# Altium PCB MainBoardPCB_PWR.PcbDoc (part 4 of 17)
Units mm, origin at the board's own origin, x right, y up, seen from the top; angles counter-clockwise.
Board outline 333.63 x 349.38 mm, 16 copper layers (L1, L2 (GND), L3 (Sign), L4 (GND), L5 (Sign), L6 (PWR/GND), L7(PWR/GND), L8 (PWR/GND), L9 (PWR/GND), L10 (PWR/GND), L11 (PWR/GND), L12 (Sign), L13 (GND), L14 (Sign), L15 (GND), L16), stack 2.503 mm thick; 2187 components, 1615 nets, 7987 pads, 1695 vias.
Unrouted connection lines stored in the file: 4757.
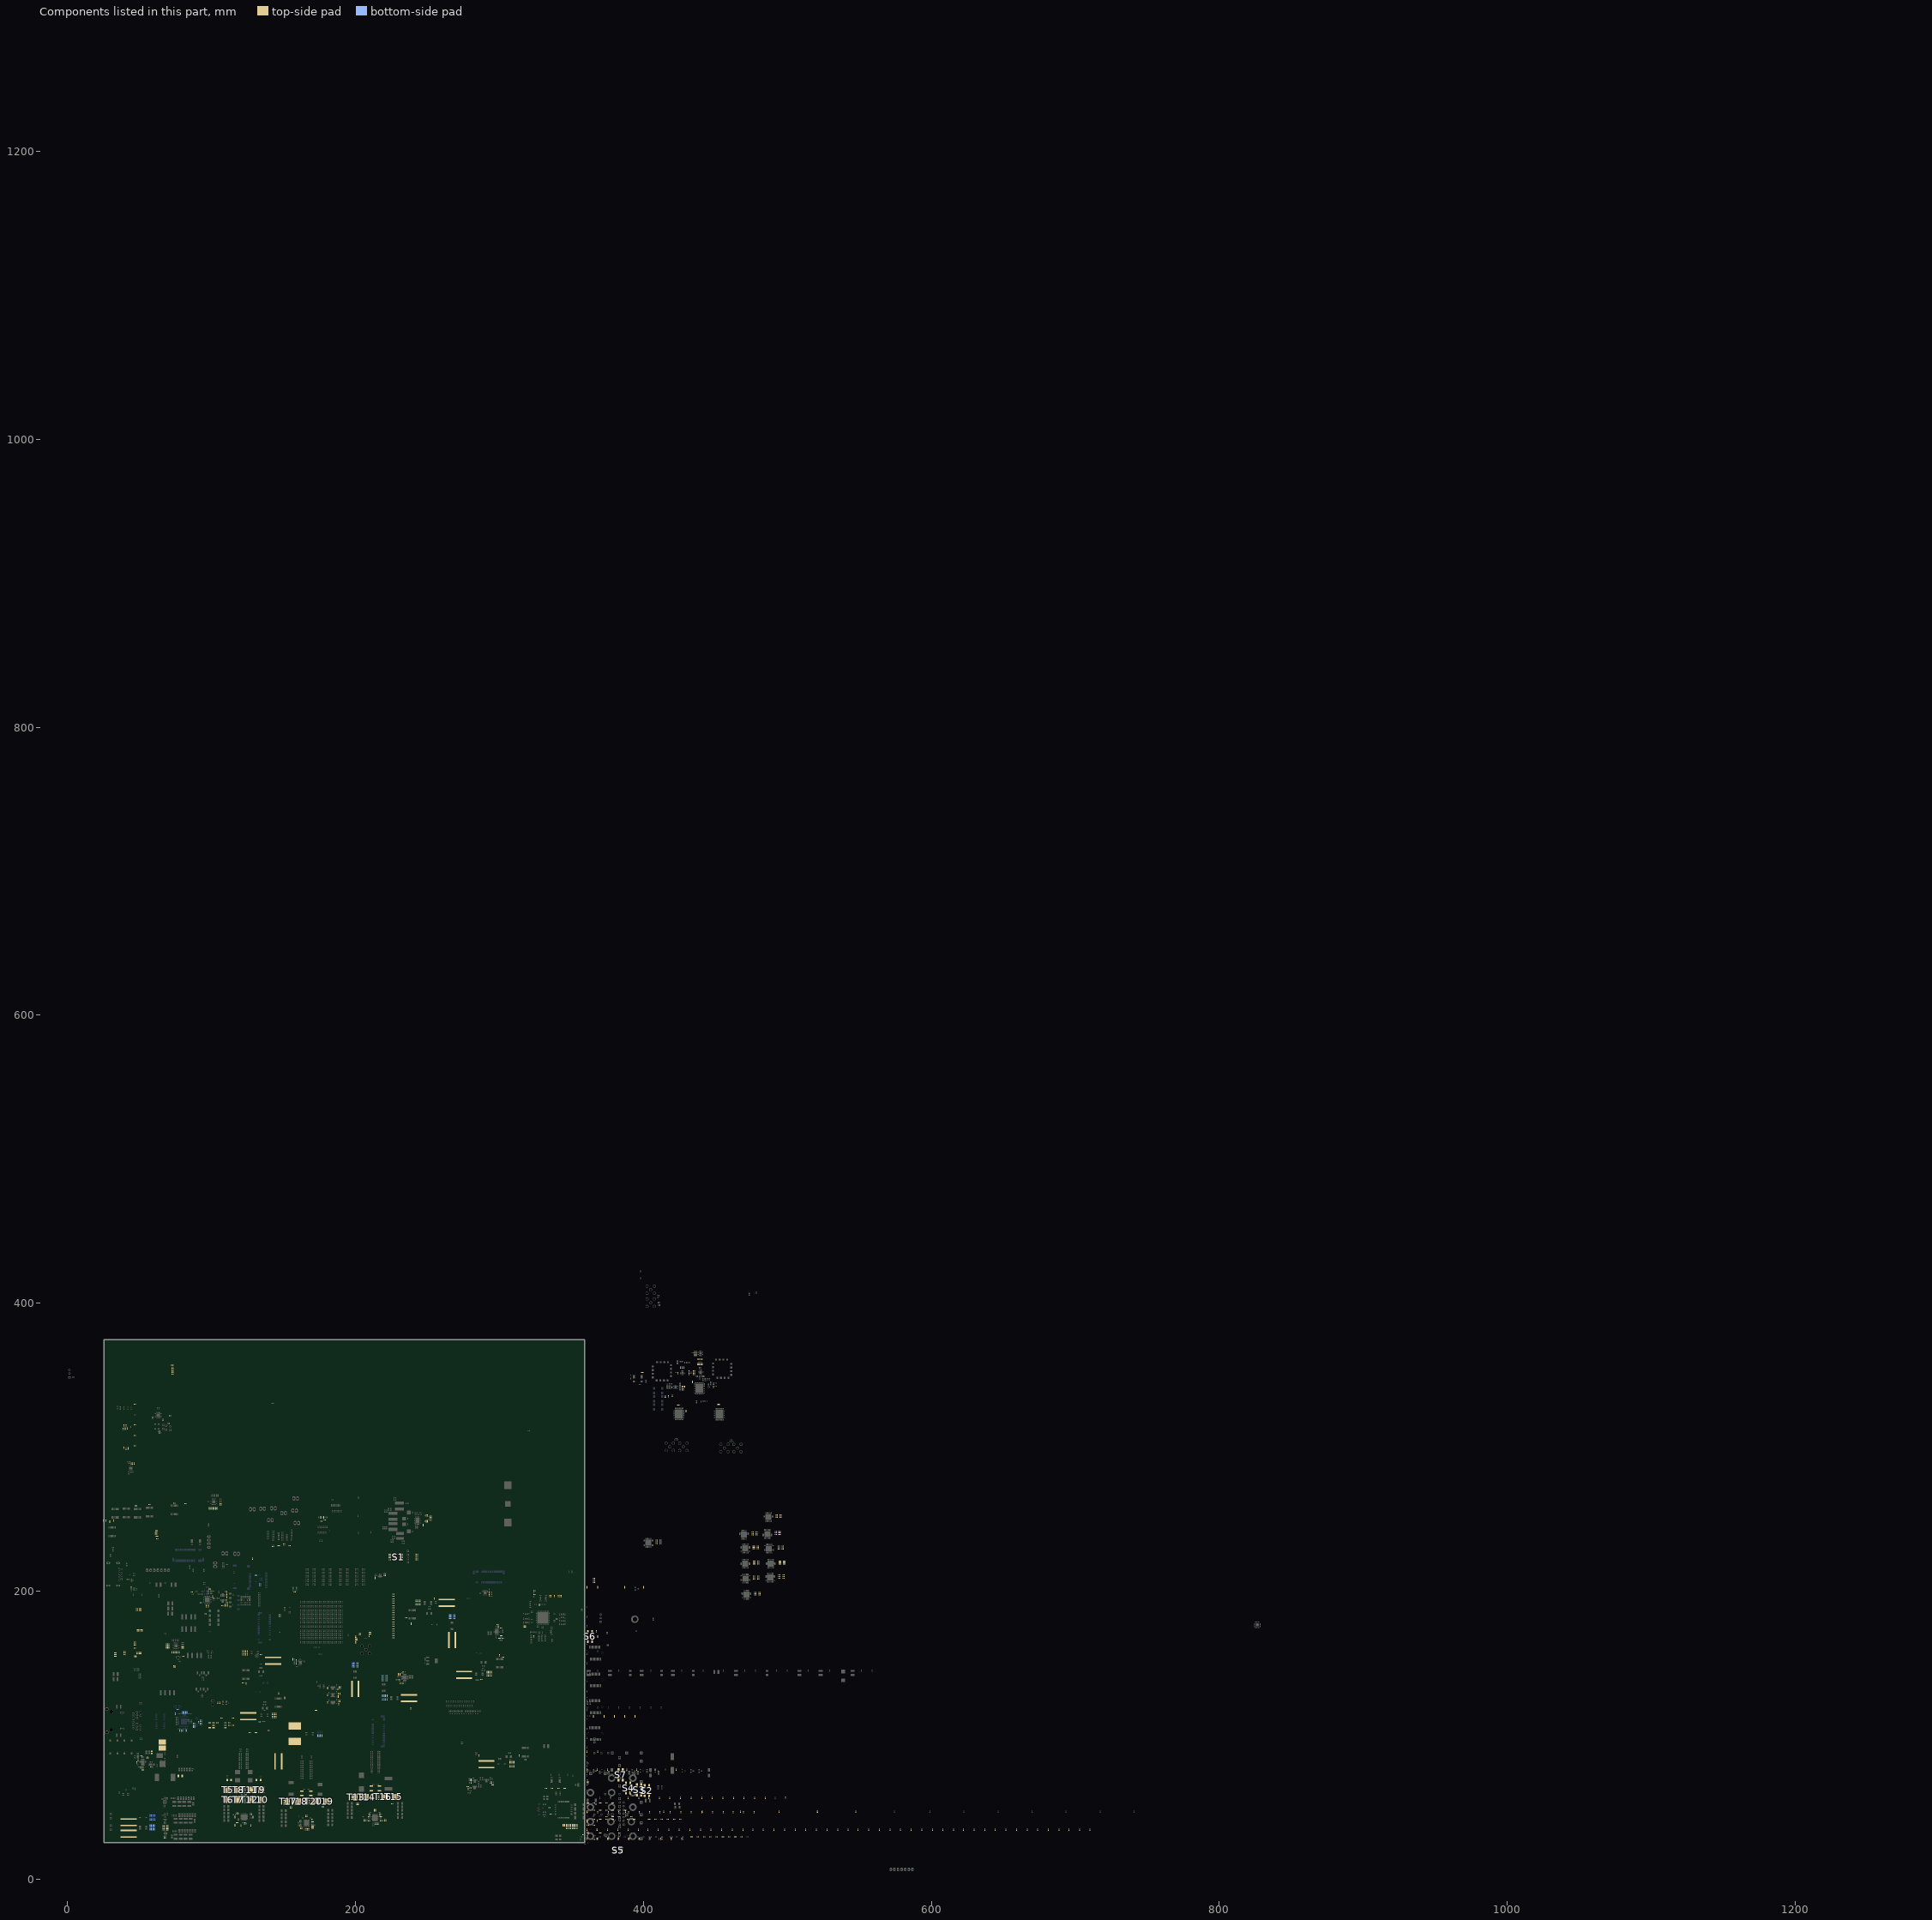
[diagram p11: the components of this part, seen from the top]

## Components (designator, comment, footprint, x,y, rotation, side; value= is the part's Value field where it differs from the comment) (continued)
R122 "30R" "RES 0402/1005 RF" 86.36,199.263 r0 top
R123 "4.7kR" "RES 0402/1005 RF" 107.442,189.738 r0 top
R124 "1kR" "RES 0402/1005 RF" 172.593,117.221 r180 top
R125 "10kR" "RES 0402/1005 RF" 339.728,180.764 r180 top
R126 "100R" "RES 0402/1005 RF" 335.899,196.61 r270 top
R127 "0R" "RES 0402/1005 RF" 367.995,40.538 r90 top
R128 "10kR" "RES 0402/1005 RF" 317.608,174.88 r180 top
R129 "10kR" "RES 0402/1005 RF" 317.608,175.819 r180 top
R130 "0R" "RES 0402/1005 RF" 334.902,196.597 r270 top
R131 "0R" "RES 0402/1005 RF" 338.144,196.597 r270 top
R132 "0R" "RES 0402/1005 RF" 342.005,196.483 r90 top
R133 "0R" "RES 0402/1005 RF" 343.021,196.483 r90 top
R134 "0R" "RES 0402/1005 RF" 340.998,196.528 r90 top
R135 "4.7kR" "RES 0402/1005 RF" 47.255,154.305 r0 top
R136 "4.7kR" "RES 0402/1005 RF" 46.99,155.067 r0 top
R137 "4.7kR" "RES 0402/1005 RF" 46.805,160.274 r0 top
R138 "4.7kR" "RES 0402/1005 RF" 33.216,154.695 r0 top
R139 "0R" "RES 0402/1005 RF" 360.883,40.538 r90 top
R140 "2.2R" "RES 0402/1005 RF" 55.575,84.026 r0 top
R141 "0R" "RES 0402/1005 RF" 50.549,156.46 r0 top
R142 "0R" "RES 0402/1005 RF" 50.549,157.494 r0 top
R143 "0R" "RES 0402/1005 RF" 48.575,156.478 r0 top
R144 "0R" "RES 0402/1005 RF" 48.575,157.494 r0 top
R145 "4.7kR" "RES 0402/1005 RF" 46.736,164.465 r0 top
R146 "4.7kR" "RES 0402/1005 RF" 46.736,162.56 r0 top
R147 "4.7kR" "RES 0402/1005 RF" 46.736,163.449 r0 top
R148 "4.7kR" "RES 0402/1005 RF" 33.216,156.981 r0 top
R149 "196kR" "RES 0402/1005 RF" 52.232,84.777 r0 top
R150 "22k" "RES 0402/1005 RF" 52.332,75.895 r0 top
R151 "0R" "RES 0402/1005 RF" 51.393,173.303 r0 top
R152 "0R" "RES 0402/1005 RF" 51.346,172.287 r0 top
R153 "0R" "RES 0402/1005 RF" 48.98,173.303 r0 top
R154 "0R" "RES 0402/1005 RF" 48.98,172.287 r0 top
R155 "4.7kR" "RES 0402/1005 RF" 39.693,158.115 r0 top
R156 "4.7kR" "RES 0402/1005 RF" 39.693,157.099 r0 top
R157 "4.7kR" "RES 0402/1005 RF" 39.684,155.829 r0 top
R158 "4.7kR" "RES 0402/1005 RF" 33.216,155.956 r0 top
R159 "10kR" "RES 0402/1005 RF" 51.307,85.787 r0 top
R160 "910R" "RES 0402/1005 RF" 51.883,77.43 r90 top
R161 "0R" "RES 0402/1005 RF" 50.473,187.654 r0 top
R162 "0R" "RES 0402/1005 RF" 50.473,186.638 r0 top
R163 "0R" "RES 0402/1005 RF" 48.234,187.654 r0 top
R164 "0R" "RES 0402/1005 RF" 48.234,186.638 r0 top
R165 "100R" "RES 0402/1005 RF" 178.738,249.428 r0 top
R166 "100R" "RES 0402/1005 RF" 176.394,248.666 r0 top
R167 "100R" "RES 0402/1005 RF" 178.029,251.222 r90 top
R168 "100R" "RES 0402/1005 RF" 175.87,251.222 r90 top
R169 "100R" "RES 0402/1005 RF" 150.495,232.621 r0 top
R170 "100R" "RES 0402/1005 RF" 146.685,231.605 r0 top
R171 "100R" "RES 0402/1005 RF" 154.292,231.605 r0 top
R172 "100R" "RES 0402/1005 RF" 142.748,230.97 r0 top
R173 "500R" "RES 0402/1005 RF" 360.883,28.042 r90 top
R174 "0mR" "RES 0402/1005 RF" 242.95,190.832 r270 top
R175 "0mR" "RES 0402/1005 RF" 241.934,190.832 r270 top
R176 "0mR" "RES 0402/1005 RF" 245.03,190.832 r270 top
R177 "0mR" "RES 0402/1005 RF" 244.014,190.832 r270 top
R178 "0mR" "RES 0402/1005 RF" 242.95,193.209 r90 top
R179 "0mR" "RES 0402/1005 RF" 241.934,193.209 r90 top
R180 "0mR" "RES 0402/1005 RF" 245.03,193.209 r90 top
R181 "0mR" "RES 0402/1005 RF" 244.014,193.209 r90 top
R182 "1.02kR" "RES 0402/1005 RF" 254.912,194.739 r90 top
R183 "0mR" "RES 0402/1005 RF" 293.357,143.679 r90 top
R184 "0mR" "RES 0402/1005 RF" 294.357,143.679 r90 top
R185 "0mR" "RES 0402/1005 RF" 291.357,143.679 r90 top
R186 "0mR" "RES 0402/1005 RF" 292.357,143.679 r90 top
R187 "0mR" "RES 0402/1005 RF" 293.357,141.493 r270 top
R188 "0mR" "RES 0402/1005 RF" 294.357,141.493 r270 top
R189 "0mR" "RES 0402/1005 RF" 291.357,141.493 r270 top
R190 "0mR" "RES 0402/1005 RF" 292.357,141.493 r270 top
R191 "1.02kR" "RES 0402/1005 RF" 287.374,138.68 r0 top
R192 "0mR" "RES 0402/1005 RF" 122.794,156.081 r270 top
R193 "0mR" "RES 0402/1005 RF" 121.735,156.081 r270 top
R194 "0mR" "RES 0402/1005 RF" 124.91,156.081 r270 top
R195 "0mR" "RES 0402/1005 RF" 123.852,156.081 r270 top
R196 "0mR" "RES 0402/1005 RF" 122.794,158.113 r90 top
R197 "0mR" "RES 0402/1005 RF" 121.735,158.113 r90 top
R198 "0mR" "RES 0402/1005 RF" 124.91,158.113 r90 top
R199 "0mR" "RES 0402/1005 RF" 123.852,158.113 r90 top
R200 "1.02kR" "RES 0402/1005 RF" 134.297,155.956 r0 top
R201 "0mR" "RES 0402/1005 RF" 144.008,114.727 r90 top
R202 "0mR" "RES 0402/1005 RF" 144.958,114.727 r90 top
R203 "0mR" "RES 0402/1005 RF" 142.088,114.727 r90 top
R204 "0mR" "RES 0402/1005 RF" 143.053,114.732 r90 top
R205 "0mR" "RES 0402/1005 RF" 144.008,112.571 r270 top
R206 "0mR" "RES 0402/1005 RF" 144.958,112.571 r270 top
R207 "0mR" "RES 0402/1005 RF" 142.088,112.568 r270 top
R208 "0mR" "RES 0402/1005 RF" 143.053,112.568 r270 top
R209 "1.02kR" "RES 0402/1005 RF" 133.501,109.15 r180 top
R210 "0mR" "RES 0402/1005 RF" 309.27,81.218 r90 top
R211 "0mR" "RES 0402/1005 RF" 310.314,81.218 r90 top
R212 "12.5k" "RES 0402/1005 RF" 251.788,251.574 r90 top
R213 "0mR" "RES 0402/1005 RF" 307.166,81.218 r90 top
R214 "10kR" "RES 0402/1005 RF" 252.738,251.574 r270 top
R215 "0mR" "RES 0402/1005 RF" 308.227,81.218 r90 top
R216 "31.2kR" "RES 0402/1005 RF" 249.13,252.624 r270 top
R217 "0mR" "RES 0402/1005 RF" 309.27,78.437 r270 top
R218 "10kR" "RES 0402/1005 RF" 250.096,252.624 r270 top
R219 "0mR" "RES 0402/1005 RF" 310.314,78.437 r270 top
R220 "4.99kR" "RES 0402/1005 RF" 249.13,248.499 r270 top
R221 "0mR" "RES 0402/1005 RF" 307.166,78.441 r270 top
R222 "0mR" "RES 0402/1005 RF" 308.227,78.441 r270 top
R223_I2C_Bridge "1kR" "RES 0402/1005 RF" 106.426,260.867 r0 top (schematic designator R223)
R223_I2C_Bridge_2 "1kR" "RES 0402/1005 RF" 547.548,46.787 r90 top (schematic designator R223)
R223_I2C_Bridge_3 "1kR" "RES 0402/1005 RF" 79.952,161.248 r0 top (schematic designator R223)
R224_I2C_Bridge "1kR" "RES 0402/1005 RF" 106.426,259.812 r0 top (schematic designator R224)
R224_I2C_Bridge_2 "1kR" "RES 0402/1005 RF" 520.878,46.787 r90 top (schematic designator R224)
R224_I2C_Bridge_3 "1kR" "RES 0402/1005 RF" 79.952,160.274 r0 top (schematic designator R224)
R225_I2C_Bridge "1kR" "RES 0402/1005 RF" 103.886,257.487 r270 top (schematic designator R225)
R225_I2C_Bridge_2 "1kR" "RES 0402/1005 RF" 494.208,46.787 r90 top (schematic designator R225)
R225_I2C_Bridge_3 "1kR" "RES 0402/1005 RF" 77.471,157.607 r270 top (schematic designator R225)
R226_I2C_Bridge "1kR" "RES 0402/1005 RF" 102.85,257.487 r270 top (schematic designator R226)
R226_I2C_Bridge_2 "1kR" "RES 0402/1005 RF" 467.538,46.787 r90 top (schematic designator R226)
R226_I2C_Bridge_3 "1kR" "RES 0402/1005 RF" 76.506,157.607 r270 top (schematic designator R226)
R227_I2C_Bridge "1kR" "RES 0402/1005 RF" 101.85,257.487 r270 top (schematic designator R227)
R227_I2C_Bridge_2 "1kR" "RES 0402/1005 RF" 440.893,46.787 r90 top (schematic designator R227)
R227_I2C_Bridge_3 "1kR" "RES 0402/1005 RF" 75.54,157.607 r270 top (schematic designator R227)
R228 "1.02kR" "RES 0402/1005 RF" 285.883,85.729 r90 top
R229 "0mR" "RES 0402/1005 RF" 59.385,37.078 r90 bottom
R230 "0mR" "RES 0402/1005 RF" 60.465,37.078 r90 bottom
R231_SPI_bridge1 "1kR" "RES 0402/1005 RF" 238.618,177.387 r90 top (schematic designator R231)
R231_SPI_bridge2 "1kR" "RES 0402/1005 RF" 411.039,398.754 r0 top (schematic designator R231)
R231_SPI_bridge3 "1kR" "RES 0402/1005 RF" 74.237,261.112 r180 top (schematic designator R231)
R232_SPI_bridge1 "1kR" "RES 0402/1005 RF" 235.247,181.451 r0 top (schematic designator R232)
R232_SPI_bridge2 "1kR" "RES 0402/1005 RF" 410.716,400.405 r0 top (schematic designator R232)
R232_SPI_bridge3 "1kR" "RES 0402/1005 RF" 62.103,238.125 r0 top (schematic designator R232)
R233_SPI_bridge1 "1kR" "RES 0402/1005 RF" 299.974,155.533 r270 top (schematic designator R233)
R233_SPI_bridge2 "1kR" "RES 0402/1005 RF" 420.04,335.691 r90 top (schematic designator R233)
R233_SPI_bridge3 "1kR" "RES 0402/1005 RF" 96.012,184.333 r180 top (schematic designator R233)
R234_SPI_bridge1 "1kR" "RES 0402/1005 RF" 302.583,154.136 r180 top (schematic designator R234)
R234_SPI_bridge2 "1kR" "RES 0402/1005 RF" 415.158,335.114 r90 top (schematic designator R234)
R234_SPI_bridge3 "1kR" "RES 0402/1005 RF" 61.838,241.935 r0 top (schematic designator R234)
R235_SPI_bridge1 "1kR" "RES 0402/1005 RF" 121.772,136.265 r0 top (schematic designator R235)
R235_SPI_bridge2 "1kR" "RES 0402/1005 RF" 417.444,335.437 r90 top (schematic designator R235)
R235_SPI_bridge3 "1kR" "RES 0402/1005 RF" 62.288,236.453 r0 top (schematic designator R235)
R236_SPI_bridge1 "1kR" "RES 0402/1005 RF" 123.952,135.763 r90 top (schematic designator R236)
R236_SPI_bridge2 "1kR" "RES 0402/1005 RF" 433.984,345.313 r90 top (schematic designator R236)
R236_SPI_bridge3 "1kR" "RES 0402/1005 RF" 47.498,259.207 r180 top (schematic designator R236)
R237_SPI_bridge1 "1kR" "RES 0402/1005 RF" 151.003,125.857 r90 top (schematic designator R237)
R237_SPI_bridge2 "1kR" "RES 0402/1005 RF" 32.004,248.92 r90 top (schematic designator R237)
R237_SPI_bridge3 "1kR" "RES 0402/1005 RF" 61.503,240.792 r0 top (schematic designator R237)
R238_SPI_bridge1 "1kR" "RES 0402/1005 RF" 146.685,129.032 r270 top (schematic designator R238)
R238_SPI_bridge2 "1kR" "RES 0402/1005 RF" 29.464,248.285 r90 top (schematic designator R238)
R238_SPI_bridge3 "1kR" "RES 0402/1005 RF" 56.896,260.096 r180 top (schematic designator R238)
R239_SPI_bridge1 "1kR" "RES 0402/1005 RF" 313.893,85.725 r270 top (schematic designator R239)
R239_SPI_bridge2 "1kR" "RES 0402/1005 RF" 26.543,249.047 r90 top (schematic designator R239)
R239_SPI_bridge3 "1kR" "RES 0402/1005 RF" 61.503,239.649 r0 top (schematic designator R239)
R240_SPI_bridge1 "1kR" "RES 0402/1005 RF" 318.028,83.058 r0 top (schematic designator R240)
R240_SPI_bridge2 "1kR" "RES 0402/1005 RF" 25.019,248.92 r90 top (schematic designator R240)
R240_SPI_bridge3 "1kR" "RES 0402/1005 RF" 81.973,260.858 r180 top (schematic designator R240)
R241 "0mR" "RES 0402/1005 RF" 411.963,28.042 r90 top
R242 "0mR" "RES 0402/1005 RF" 404.597,28.042 r90 top
R243 "0mR" "RES 0402/1005 RF" 397.205,28.042 r90 top
R244 "0mR" "RES 0402/1005 RF" 389.839,28.042 r90 top
R245 "100R" "RES 0402/1005 RF" 439.318,355.092 r180 top
R246 "120R" "RES 0402/1005 RF" 440.303,361.061 r180 top
R247 "127R" "RES 0402/1005 RF" 440.303,357.251 r180 top
R248 "127R" "RES 0402/1005 RF" 438.202,357.251 r0 top
R249 "120R" "RES 0402/1005 RF" 438.202,361.061 r180 top
R250 "82.5R" "RES 0402/1005 RF" 440.303,358.267 r180 top
R251 "82.5R" "RES 0402/1005 RF" 438.202,358.267 r0 top
R252 "1kR" "RES 0402/1005 RF" 435.635,366.083 r90 top
R253 "1kR" "RES 0402/1005 RF" 435.635,364.079 r270 top
R254 "1kR" "RES 0402/1005 RF" 436.651,366.083 r270 top
R255 "1kR" "RES 0402/1005 RF" 436.651,364.079 r90 top
R256 "120R" "RES 0402/1005 RF" 431.825,350.774 r90 top
R257 "49.9R" "RES 0402/1005 RF" 423.951,351.467 r90 top
R258 "120R" "RES 0402/1005 RF" 431.825,352.711 r90 top
R259 "82.5R" "RES 0402/1005 RF" 435.635,352.711 r270 top
R260 "82.5R" "RES 0402/1005 RF" 435.635,350.774 r90 top
R261 "127R" "RES 0402/1005 RF" 434.619,352.711 r270 top
R262 "127R" "RES 0402/1005 RF" 434.619,350.774 r90 top
R263 "60.4kR" "RES 0402/1005 RF" 425.602,355.288 r270 top
R264 "0mR" "RES 0402/1005 RF" 428.112,355.288 r270 top
R265 "0mR" "RES 0402/1005 RF" 426.887,355.288 r270 top
R266 "84.5kR" "RES 0402/1005 RF" 383.235,32.182 r0 top
R267 "4.7kR" "RES 0402/1005 RF" 370.04,32.182 r0 top
R268 "2R" "RES 0402/1005 RF" 120.402,37.326 r90 top
R269 "1.02kR" "RES 0402/1005 RF" 361.391,32.182 r0 top
R270 "160R" "RES 0402/1005 RF" 238.506,118.618 r270 top
R271 "5kR" "RES 0402/1005 RF" 117.796,39.126 r180 top
R272 "2R" "RES 0402/1005 RF" 122.978,38.69 r270 top
R273 "12kR" "RES 0402/1005 RF" 118.596,41.473 r270 top
R274 "10kR" "RES 0402/1005 RF" 250.096,248.503 r90 top
R275 "47kR" "RES 0402/1005 RF" 121.202,58.572 r180 top
R276 "4.7kR" "RES 0402/1005 RF" 387.363,47.739 r0 top
R277 "12kR" "RES 0402/1005 RF" 128.799,43.024 r90 top
R278 "12kR" "RES 0402/1005 RF" 116.439,43.024 r90 top
R279 "0mR" "RES 0402/1005 RF" 383.045,47.739 r0 top
R280 "47kR" "RES 0402/1005 RF" 123.777,58.572 r0 top
R281 "0mR" "RES 0402/1005 RF" 382.981,28.042 r90 top
R282 "0mR" "RES 0402/1005 RF" 378.714,47.739 r0 top
R283 "0mR" "RES 0402/1005 RF" 374.383,47.739 r0 top
R284 "18.2k (1MHz)" "RES 0402/1005 RF" 247.126,245.841 r90 top
R285 "2R" "RES 0402/1005 RF" 201.462,51.702 r0 top
R286 "0mR" "RES 0402/1005 RF" 370.053,47.739 r0 top
R287 "49.9kR" "RES 0402/1005 RF" 205.838,40.864 r90 top
R288 "Resistor_1210" RES_1210 211.045,63.039 r270 top value=3.6R
R289 "2R" "RES 0402/1005 RF" 213.795,38.516 r270 top
R290 "10kR" "RES 0402/1005 RF" 206.788,40.864 r270 top
R291 "150R" "RES 0402/1005 RF" 365.722,47.739 r0 top
R292 "Resistance" "RES 0402/1005 RF" 213.195,47.846 r270 top
R293 "0mR" "RES 0402/1005 RF" 214.795,38.516 r90 top
R294 "0mR" "RES 0402/1005 RF" 215.795,38.516 r90 top
R295 "12kR" "RES 0402/1005 RF" 209.441,43.359 r0 top
R296 "12kR" "RES 0402/1005 RF" 217.555,43.359 r180 top
R297 "10kR" "RES 0402/1005 RF" 221.201,40.765 r90 top
R298 "Resistor_1210" RES_1210 216.76,63.039 r270 top value=3.6R
R299 "47kR" "RES 0402/1005 RF" 214.045,47.846 r270 top
R300 "10kR" "RES 0402/1005 RF" 220.17,40.765 r270 top
R301 "150R" "RES 0402/1005 RF" 391.655,43.434 r0 top
R302 "1.4kR" "RES 0201/0603" 170.009,41.515 r180 top
R303 "2R" "RES 0402/1005 RF" 155.178,49.178 r0 top
R304 "0mR" "RES 0402/1005 RF" 175.712,99.689 r270 bottom
R305 "100R" "RES 0402/1005 RF" 383.019,43.434 r0 top
R306 "Resistor_1210" RES_1210 162.816,59.629 r270 top value=3.6R
R307 "2R" "RES 0402/1005 RF" 165.608,34.537 r270 top
R308 "100R" "RES 0402/1005 RF" 378.689,43.434 r0 top
R309 "100R" "RES 0402/1005 RF" 374.358,43.434 r0 top
R310 "0mR" "RES 0402/1005 RF" 166.533,34.537 r90 top
R311 "100R" "RES 0402/1005 RF" 361.391,67.488 r0 top
R312 "0mR" "RES 0402/1005 RF" 167.448,34.537 r90 top
R313 "12kR" "RES 0402/1005 RF" 161.743,40.015 r0 top
R314 "12kR" "RES 0402/1005 RF" 170.224,39.685 r180 top
R315 "196kR" "RES 0402/1005 RF" 170.224,36.103 r0 top
R316 "Resistor_1210" RES_1210 169.006,59.629 r270 top value=3.6R
R317 "47kR" "RES 0402/1005 RF" 166.458,43.718 r270 top
R318 "27kR" "RES 0402/1005 RF" 170.224,35.175 r180 top
R319 "10kR" "RES 0402/1005 RF" 92.075,109.935 r90 bottom
R320 "10kR" "RES 0402/1005 RF" 92.075,107.893 r270 bottom
R321 "100R" "RES 0402/1005 RF" 90.932,109.035 r90 bottom
R322 "5.76kR" "RES 0402/1005 RF" 88.392,107.765 r90 bottom
R323 "5.76kR" "RES 0402/1005 RF" 87.376,105.915 r270 bottom
R324 "100kR" "RES 0805/2012 RF" 58.578,87.994 r270 top
R325 "2.49kR" "RES 0402/1005 RF" 93.028,109.924 r270 bottom
R326 "2.49kR" "RES 0402/1005 RF" 93.028,107.893 r90 bottom
R327 "2.49kR" "RES 0402/1005 RF" 87.376,107.765 r270 bottom
R328 "2.49kR" "RES 0402/1005 RF" 88.392,105.915 r90 bottom
R329 "100R" "RES 0402/1005 RF" 78.022,103.113 r270 bottom
R330 "100R" "RES 0402/1005 RF" 79.022,103.113 r270 bottom
R331 "100R" "RES 0402/1005 RF" 80.022,103.113 r270 bottom
R332 "100R" "RES 0402/1005 RF" 82.522,103.113 r90 bottom
R333 "2.2kR" "RES 0402/1005 RF" 80.007,115.766 r270 bottom
R334 "11kR" "RES 0402/1005" 74.93,114.741 r90 bottom
R335 "1MR" "RES 0402/1005 RF" 76.516,117.836 r180 bottom
R336 "2.2kR" "RES 0402/1005 RF" 83.038,115.766 r270 bottom
R337 "2.2kR" "RES 0402/1005 RF" 81.022,115.766 r270 bottom
R338 "2.2kR" "RES 0402/1005 RF" 82.022,115.766 r270 bottom
R339 "105kR" "RES 0402/1005 RF" 110.692,198.11 r90 top
R340 "10kR" "RES 0402/1005 RF" 110.226,199.669 r0 top
R341 "15kR" "RES 0402/1005 RF" 110.692,196.185 r90 top
R342 "105kR" "RES 0402/1005 RF" 110.392,193.552 r90 top
R343 "10kR" "RES 0402/1005 RF" 110.957,190.202 r270 top
R344 "15kR" "RES 0402/1005 RF" 110.84,192.073 r180 top
R345 "0R" "RES 0402/1005 RF" 109.572,190.186 r90 top
R346 "4.7kR" "RES 0402/1005 RF" 70.254,316.535 r0 top
R347 "4.7kR" "RES 0402/1005 RF" 147.389,182.53 r0 top
R348 "4.7kR" "RES 0402/1005 RF" 147.447,183.642 r0 top
R349 "4.7kR" "RES 0402/1005 RF" 242.639,221.742 r0 top
R350 "4.7kR" "RES 0402/1005 RF" 242.639,223.054 r0 top
R351 "4.7kR" "RES 0402/1005 RF" 242.639,224.367 r0 top
R352 "4.7kR" "RES 0402/1005 RF" 242.639,225.679 r0 top
R353 "4.7kR" "RES 0402/1005 RF" 39.301,299.653 r90 top
R354 "4.7kR" "RES 0402/1005 RF" 63.754,311.201 r0 top
R355 "4.7kR" "RES 0402/1005 RF" 64.135,309.931 r0 top
R356 "4.7kR" "RES 0402/1005 RF" 42.028,299.203 r270 top
R357 "4.7kR" "RES 0402/1005 RF" 40.728,298.753 r90 top
R358 "499R" "RES 0402/1005 RF" 224.045,221.86 r180 top
R359 "499R" "RES 0402/1005 RF" 223.845,223.139 r180 top
R360 "499R" "RES 0402/1005 RF" 223.845,224.409 r180 top
R361 "499R" "RES 0402/1005 RF" 223.845,225.679 r180 top
R362 "30R" "RES 0402/1005 RF" 38.539,312.801 r90 top
R363 "4.7kR" "RES 0402/1005 RF" 39.301,315.156 r90 top
R364 "4.7kR" "RES 0402/1005 RF" 40.078,312.87 r90 top
R365 "4.7kR" "RES 0402/1005 RF" 41.46,312.928 r90 top
R366 "10kR" "RES 0402/1005 RF" 40.825,315.087 r90 top
R367 "4.7kR" "RES 0402/1005 RF" 71.27,321.691 r0 top
R368 "261R" "RES 0402/1005 RF" 46.863,329.819 r180 top
R369 "10kR" "RES 0402/1005 RF" 66.317,318.948 r90 top
R370 "10kR" "RES 0402/1005 RF" 46.863,300.863 r180 top
R371 "10kR" "RES 0402/1005 RF" 46.863,308.229 r180 top
R372 "8.06kR" "RES 0402/1005 RF" 46.863,315.595 r180 top
R373 "10kR" "RES 0402/1005 RF" 59.078,320.472 r90 top
R374 "4.7MR" "RES 0402/1005 RF" 157.874,199.339 r0 top
R375 "40.2R" "RES 0402/1005 RF" 128.637,222.542 r270 top
R376 "0R" "RES 0402/1005 RF" 92.603,192.052 r180 top
R377 "0R" "RES 0402/1005 RF" 96.278,189.529 r270 top
R378 "0R" "RES 0402/1005 RF" 97.778,189.529 r270 top
R379 "8.06kR" "RES 0402/1005 RF" 100.851,196.372 r270 top
R380 "4.22kR" "RES 0402/1005 RF" 44.348,202.539 r270 top
R381 "4.7kR" "RES 0402/1005 RF" 133.789,205.105 r180 bottom
R382 "4.7kR" "RES 0402/1005 RF" 133.8,203.835 r180 bottom
R383 "10kR" "RES 0402/1005 RF" 130.937,211.074 r0 bottom
R384 "71.5R" "RES 0402/1005 RF" 365.76,208.915 r0 top
R385 "71.5R" "RES 0402/1005 RF" 365.76,207.899 r0 top
R386 "8.87kR" "RES 0402/1005 RF" 365.76,206.883 r0 top
R387 "5.1kR" "RES 0402/1005 RF" 365.76,205.867 r0 top
R388 "0mR" "RES 0402/1005 RF" 176.728,99.689 r270 bottom
R389 "0mR" "RES 0402/1005 RF" 174.687,99.695 r270 bottom
R390 "0mR" "RES 0402/1005 RF" 173.68,99.689 r270 bottom
R391 "75kR" "RES 0402/1005 RF" 188.725,132.945 r90 top
R392 "100kR" "RES 0402/1005 RF" 189.711,132.945 r90 top
R393 "15kR" "RES 0402/1005 RF" 187.696,131.995 r90 top
R394 "51.1kR" "RES 0402/1005 RF" 188.22,128.702 r90 top
R395 "10kR" "RES 0402/1005 RF" 189.244,128.704 r90 top
R396 "15kR" "RES 0402/1005 RF" 188.22,126.719 r90 top
R397 "21.5kR" "RES 0402/1005 RF" 188.266,123.575 r90 top
R398 "10kR" "RES 0402/1005 RF" 189.244,123.575 r90 top
R399 "15kR" "RES 0402/1005 RF" 188.266,121.609 r90 top
R400 "0mR" "RES 0402/1005 RF" 375.615,28.042 r90 top
R401 "10k" "RES 0402/1005 RF" 345.349,37.41 r90 top
R402 "0R" "RES 0402/1005 RF" 348.539,37.41 r270 top
R403 "0R" "RES 0402/1005 RF" 348.539,35.378 r90 top
R404 "0R" "RES 0402/1005 RF" 349.603,37.41 r270 top
R405 "0R" "RES 0402/1005 RF" 349.603,35.378 r90 top
R406 "0R" "RES 0402/1005 RF" 347.476,37.41 r270 top
R407 "0R" "RES 0402/1005 RF" 347.476,35.378 r90 top
R408 "0R" "RES 0402/1005 RF" 346.412,37.41 r270 top
R409 "0R" "RES 0402/1005 RF" 346.412,35.378 r90 top
R410 "10k" "RES 0402/1005 RF" 344.285,37.41 r90 top
R411 "0R" "RES 0402/1005 RF" 351.73,37.41 r270 top
R412 "0R" "RES 0402/1005 RF" 351.73,35.378 r90 top
R413 "0R" "RES 0402/1005 RF" 353.857,37.41 r270 top
R414 "0R" "RES 0402/1005 RF" 353.857,35.378 r90 top
R415 "0R" "RES 0402/1005 RF" 350.666,37.41 r270 top
R416 "0R" "RES 0402/1005 RF" 350.666,35.378 r90 top
R417 "10k" "RES 0402/1005 RF" 345.364,62.879 r0 top
R418 "0R" "RES 0402/1005 RF" 352.794,37.41 r270 top
R419 "2kR" "RES 0402/1005 RF" 340.919,62.879 r0 top
R420 "10k" "RES 0402/1005 RF" 336.601,62.879 r0 top
R421 "0R" "RES 0402/1005 RF" 352.794,35.378 r90 top
R422 "10k" "RES 0402/1005 RF" 332.283,62.879 r0 top
R423 "12kR" "RES 0402/1005 RF" 334.765,49.731 r0 top
R424 "1kR" "RES 0402/1005 RF" 335.712,45.043 r0 top
R425 "4.7kR" "RES 0402/1005 RF" 74.177,148.171 r0 top
R426 "4.7kR" "RES 0402/1005 RF" 74.295,147.154 r0 top
R427 "1kR" "RES 0402/1005 RF" 365.722,37.401 r0 top
R428 "1kR" "RES 0402/1005 RF" 368.249,28.042 r90 top
R429 "0mR" "RES 0402/1005 RF" 80.518,154.631 r0 top
R430_5V_to_3V3_for_FTDI "105kR" "RES 0402/1005 RF" 45.226,288.642 r90 top (schematic designator R430)
R430_U_5V_to_3V31 "105kR" "RES 0402/1005 RF" 280.294,67.009 r270 top (schematic designator R430)
R430_U_5V_to_3V32 "105kR" "RES 0402/1005 RF" 279.936,63.209 r180 top (schematic designator R430)
R430_U_5V_to_3V33 "105kR" "RES 0402/1005 RF" 294.81,67.053 r90 top (schematic designator R430)
R431_5V_to_3V3_for_FTDI "100kR" "RES 0402/1005 RF" 46.267,288.642 r90 top (schematic designator R431)
R431_U_5V_to_3V31 "100kR" "RES 0402/1005 RF" 280.259,68.959 r270 top (schematic designator R431)
R431_U_5V_to_3V32 "100kR" "RES 0402/1005 RF" 278.329,62.584 r270 top (schematic designator R431)
R431_U_5V_to_3V33 "100kR" "RES 0402/1005 RF" 293.804,67.053 r90 top (schematic designator R431)
R432_5V_to_3V3_for_FTDI "15kR" "RES 0402/1005 RF" 44.222,288.642 r270 top (schematic designator R432)
R432_U_5V_to_3V31 "15kR" "RES 0402/1005 RF" 374.777,170.942 r90 top (schematic designator R432)
R432_U_5V_to_3V32 "15kR" "RES 0402/1005 RF" 278.079,64.209 r0 top (schematic designator R432)
R432_U_5V_to_3V33 "15kR" "RES 0402/1005 RF" 295.26,65.516 r180 top (schematic designator R432)
R433 "56kR" "RES 0402/1005 RF" 292.935,199.031 r90 top
R434 "10kR" "RES 0402/1005 RF" 292.935,197.103 r90 top
R435 "10kR" "RES 0402/1005 RF" 368.249,168.402 r90 top
R436 "3.57kR" "RES 0402/1005 RF" 231.436,135.975 r180 top
R437 "1.15kR" "RES 0402/1005 RF" 233.007,136.158 r90 top
R438 "3.57kR" "RES 0402/1005 RF" 230.837,142.264 r270 top
R439 "1.15kR" "RES 0402/1005 RF" 232.981,143.622 r270 top
R440 "20kR" "RES 0402/1005 RF" 230.82,138.271 r90 top
R441 "20kR" "RES 0402/1005 RF" 229.707,142.252 r270 top
R442 "100kR" "RES 0402/1005 RF" 419.739,341.667 r90 top
R443 "698kR" "RES 0805/2012 RF" 427.76,341.942 r180 top
R444 "49.9kR" "RES 0402/1005 RF" 427.76,340.092 r90 top
R445 "49.9kR" "RES 0402/1005 RF" 426.79,340.092 r90 top
R446 "120R" "RES 0402/1005 RF" 105.893,122.478 r270 top
R447 "120R" "RES 0402/1005 RF" 104.369,122.478 r270 top
R448_U_Pomiar_pradu_napiecia_1 "FCSL110R005FER" FCSL110R005FERCT-ND 42.52,31.521 r90 top (schematic designator R448)
R448_U_Pomiar_pradu_napiecia_2 "FCSL110R005FER" FCSL110R005FERCT-ND 42.52,39.488 r90 top (schematic designator R448)
R448_U_Pomiar_pradu_napiecia_3 "FCSL110R005FER" FCSL110R005FERCT-ND 199.853,132.167 r180 top (schematic designator R448)
R448_U_Pomiar_pradu_napiecia_4 "FCSL110R005FER" FCSL110R005FERCT-ND 267.157,166.04 r180 top (schematic designator R448)
R448_U_Pomiar_pradu_napiecia_5 "FCSL110R005FER" FCSL110R005FERCT-ND 146.528,81.817 r180 top (schematic designator R448)
R448_U_Pomiar_pradu_napiecia_6 "FCSL110R005FER" FCSL110R005FERCT-ND 237.191,125.705 r270 top (schematic designator R448)
R448_U_Pomiar_pradu_napiecia_7 "FCSL110R005FER" FCSL110R005FERCT-ND 263.383,191.865 r90 top (schematic designator R448)
R448_U_Pomiar_pradu_napiecia_8 "FCSL110R005FER" FCSL110R005FERCT-ND 275.463,141.817 r90 top (schematic designator R448)
R448_U_Pomiar_pradu_napiecia_9 "FCSL110R005FER" FCSL110R005FERCT-ND 142.875,151.638 r270 top (schematic designator R448)
R448_U_Pomiar_pradu_napiecia_10 "FCSL110R005FER" FCSL110R005FERCT-ND 125.603,113.157 r270 top (schematic designator R448)
R448_U_Pomiar_pradu_napiecia_11 "FCSL110R005FER" FCSL110R005FERCT-ND 291.033,79.756 r90 top (schematic designator R448)
R449 "0mR" "RES 0402/1005 RF" 73.007,355.27 r0 top
R450 "0mR" "RES 0402/1005 RF" 73.007,354.254 r0 top
R451 "0mR" "RES 0402/1005 RF" 73.007,350.698 r0 top
R452 "0mR" "RES 0402/1005 RF" 72.88,356.794 r0 top
R453 "0mR" "RES 0402/1005 RF" 73.007,352.026 r0 top
R454 "0mR" "RES 0402/1005 RF" 73.007,353.111 r0 top
R455 "0mR" "RES 0402/1005 RF" 476.822,210.411 r180 top
R456 "0mR" "RES 0402/1005 RF" 479.754,210.411 r0 top
R457 "0mR" "RES 0402/1005 RF" 58.339,37.078 r90 bottom
R458 "0mR" "RES 0402/1005 RF" 476.822,209.367 r180 top
R459 "0mR" "RES 0402/1005 RF" 57.298,37.078 r90 bottom
R460 "0mR" "RES 0402/1005 RF" 479.754,209.367 r0 top
R461 "0mR" "RES 0402/1005 RF" 59.385,34.722 r270 bottom
R462 "0mR" "RES 0402/1005 RF" 476.822,208.345 r180 top
R463 "0mR" "RES 0402/1005 RF" 60.465,34.724 r270 bottom
R464 "0mR" "RES 0402/1005 RF" 479.754,208.345 r0 top
R465 "0mR" "RES 0402/1005 RF" 58.339,34.713 r270 bottom
R466 "0mR" "RES 0402/1005 RF" 57.298,34.713 r270 bottom
R467 "0mR" "RES 0402/1005 RF" 59.434,44.111 r90 bottom
R468 "0mR" "RES 0402/1005 RF" 60.53,44.111 r90 bottom
R469 "0mR" "RES 0402/1005 RF" 68.571,163.01 r90 top
R470 "0mR" "RES 0402/1005 RF" 68.571,161.036 r270 top
R471 "0mR" "RES 0402/1005 RF" 69.587,163.01 r90 top
R472 "0mR" "RES 0402/1005 RF" 69.587,161.036 r270 top
R473 "0mR" "RES 0402/1005 RF" 70.603,163.01 r90 top
R474 "0mR" "RES 0402/1005 RF" 70.603,161.036 r270 top
R475 "0mR" "RES 0402/1005 RF" 475.839,238.894 r180 top
R476 "0mR" "RES 0402/1005 RF" 478.551,238.902 r0 top
R477 "0mR" "RES 0402/1005 RF" 475.843,239.931 r180 top
R478 "0mR" "RES 0402/1005 RF" 478.555,239.939 r0 top
R479 "0mR" "RES 0402/1005 RF" 475.843,240.976 r180 top
R480 "0mR" "RES 0402/1005 RF" 478.555,240.983 r0 top
R481 "0R" "RES 0402/1005 RF" 399.275,351.917 r0 top
R482 "150R" "RES 0402/1005 RF" 200.602,166.927 r180 top
R483 "150R" "RES 0402/1005 RF" 200.602,165.927 r180 top
R484 "71.5R" "RES 0402/1005 RF" 200.152,168.377 r270 top
R485 "71.5R" "RES 0402/1005 RF" 200.152,164.477 r90 top
R486 "8.87kR" "RES 0402/1005 RF" 203.327,170.208 r90 top
R487 "5.1kR" "RES 0402/1005 RF" 210.085,170.283 r180 top
R488 "1kR" "RES 0402/1005 RF" 210.085,171.299 r180 top
R489 "100R" "RES 0402/1005 RF" 209.635,168.811 r90 top
R490 "10kR" "RES 0402/1005 RF" 101.631,194.927 r180 top
R491 "1MR" "RES 0402/1005 RF" 98.778,201.381 r0 top
R492 "0mR" "RES 0402/1005 RF" 494.388,209.018 r180 top
R493 "0mR" "RES 0402/1005 RF" 497.283,209.024 r0 top
R494 "0mR" "RES 0402/1005 RF" 494.388,210.124 r180 top
R495 "0mR" "RES 0402/1005 RF" 497.283,210.117 r0 top
R496 "0mR" "RES 0402/1005 RF" 494.388,211.217 r180 top
R497 "0mR" "RES 0402/1005 RF" 497.283,211.217 r0 top
R498 "0R" "RES 0402/1005 RF" 130.93,101.697 r0 top
R499 "1kR" "RES 0402/1005 RF" 126.612,101.697 r0 top
R500 "0mR" "RES 0402/1005 RF" 476.965,218.647 r180 top
R501 "0mR" "RES 0402/1005 RF" 479.754,218.65 r0 top
R502 "0mR" "RES 0402/1005 RF" 476.965,219.7 r180 top
R503 "0mR" "RES 0402/1005 RF" 479.754,219.702 r0 top
R504 "0mR" "RES 0402/1005 RF" 476.965,220.747 r180 top
R505 "0mR" "RES 0402/1005 RF" 479.754,220.75 r0 top
R506 "10kR" "RES 0402/1005 RF" 226.325,181.89 r180 top
R507 "10kR" "RES 0402/1005 RF" 226.325,183.5 r180 top
R508 "0mR" "RES 0402/1005 RF" 494.829,218.656 r180 top
R509 "0mR" "RES 0402/1005 RF" 497.822,218.656 r0 top
R510 "0mR" "RES 0402/1005 RF" 494.829,219.683 r180 top
R511 "0mR" "RES 0402/1005 RF" 497.822,219.7 r0 top
R512 "0mR" "RES 0402/1005 RF" 494.83,220.7 r180 top
R513 "0mR" "RES 0402/1005 RF" 497.822,220.7 r0 top
R514 "10kR" "RES 0402/1005 RF" 226.325,178.669 r180 top
R515 "10kR" "RES 0402/1005 RF" 226.325,177.059 r180 top
R516 "0mR" "RES 0402/1005 RF" 491.927,241.49 r180 top
R517 "0mR" "RES 0402/1005 RF" 494.546,241.49 r0 top
R518 "0mR" "RES 0402/1005 RF" 491.927,240.386 r180 top
R519 "0mR" "RES 0402/1005 RF" 494.546,240.386 r0 top
R520 "0mR" "RES 0402/1005 RF" 491.929,239.273 r180 top
R521 "0mR" "RES 0402/1005 RF" 494.548,239.273 r0 top
R522 "10kR" "RES 0402/1005 RF" 226.325,167.397 r180 top
R523 "10kR" "RES 0402/1005 RF" 226.325,169.007 r180 top
R524 "0mR" "RES 0402/1005 RF" 409.272,233.02 r180 top
R525 "0mR" "RES 0402/1005 RF" 411.931,233.02 r0 top
R526 "0mR" "RES 0402/1005 RF" 409.272,234.17 r180 top
R527 "0mR" "RES 0402/1005 RF" 411.931,234.17 r0 top
R528 "0mR" "RES 0402/1005 RF" 409.272,235.364 r180 top
R529 "0mR" "RES 0402/1005 RF" 411.931,235.364 r0 top
R530 "10kR" "RES 0402/1005 RF" 226.325,172.228 r180 top
R531 "10kR" "RES 0402/1005 RF" 226.325,170.618 r180 top
R532 "75R" "RES 0402/1005 RF" 448.716,343.928 r90 top
R533 "30R" "RES 0402/1005 RF" 448.716,341.838 r90 top
R534 "100R" "RES 0402/1005 RF" 452.272,329.692 r0 top
R535 "100R" "RES 0402/1005 RF" 424.205,329.184 r0 top
R536 "150R" "RES 0402/1005 RF" 437.168,349.268 r180 top
R537 "150R" "RES 0402/1005 RF" 441.518,349.268 r180 top
R538 "1kR" "RES 0402/1005 RF" 361.391,37.401 r0 top
R539 "160R" "RES 0402/1005 RF" 429.666,325.12 r270 top
R540 "0R" "RES 0402/1005 RF" 327.843,190.483 r270 top
R541 "100R" "RES 0402/1005 RF" 368.249,88.519 r90 top
R542 "100R" "RES 0402/1005 RF" 360.883,88.519 r90 top
R543 "100R" "RES 0402/1005 RF" 324.303,200.363 r180 top
R544 "1kR" "RES 0402/1005 RF" 323.98,168.53 r90 top
R545 "49.9R" "RES 0402/1005 RF" 324.303,197.569 r180 top
R546 "10kR" "RES 0402/1005 RF" 226.325,194.772 r180 top
R547 "10kR" "RES 0402/1005 RF" 226.325,175.449 r180 top
R548 "10kR" "RES 0402/1005 RF" 226.325,193.162 r180 top
R549 "10kR" "RES 0402/1005 RF" 226.325,189.941 r180 top
R550 "10kR" "RES 0402/1005 RF" 226.325,196.383 r180 top
R551 "10kR" "RES 0402/1005 RF" 226.325,188.331 r180 top
R552 "10kR" "RES 0402/1005 RF" 226.325,185.11 r180 top
R553 "10kR" "RES 0402/1005 RF" 226.325,197.993 r180 top
R554 "10kR" "RES 0402/1005 RF" 226.325,191.552 r180 top
R555 "10kR" "RES 0402/1005 RF" 226.325,186.721 r180 top
R556 "10kR" "RES 0402/1005 RF" 226.325,180.28 r180 top
R557 "10kR" "RES 0402/1005 RF" 226.325,173.838 r180 top
R558_I2C_Bridge "1kR" "RES 0402/1005 RF" 100.85,257.487 r270 top (schematic designator R558)
R558_I2C_Bridge_2 "1kR" "RES 0402/1005 RF" 414.223,46.787 r90 top (schematic designator R558)
R558_I2C_Bridge_3 "1kR" "RES 0402/1005 RF" 74.575,157.607 r270 top (schematic designator R558)
R559_I2C_Bridge "1kR" "RES 0402/1005 RF" 99.665,257.487 r270 top (schematic designator R559)
R559_I2C_Bridge_2 "1kR" "RES 0402/1005 RF" 387.553,46.787 r90 top (schematic designator R559)
R559_I2C_Bridge_3 "1kR" "RES 0402/1005 RF" 73.609,157.607 r270 top (schematic designator R559)
R560_I2C_Bridge "1kR" "RES 0402/1005 RF" 98.552,257.487 r270 top (schematic designator R560)
R560_I2C_Bridge_2 "1kR" "RES 0402/1005 RF" 360.883,46.787 r90 top (schematic designator R560)
R560_I2C_Bridge_3 "1kR" "RES 0402/1005 RF" 72.644,157.607 r270 top (schematic designator R560)
R561 "0mR" "RES 0402/1005 RF" 198.469,149.246 r180 bottom
R562 "0mR" "RES 0402/1005 RF" 198.461,150.265 r180 bottom
R563 "0mR" "RES 0402/1005 RF" 198.469,148.246 r180 bottom
R564 "0mR" "RES 0402/1005 RF" 198.461,147.249 r180 bottom
R565 "0mR" "RES 0402/1005 RF" 201.411,149.246 r0 bottom
R566 "0mR" "RES 0402/1005 RF" 201.411,150.265 r0 bottom
R567 "0mR" "RES 0402/1005 RF" 201.411,148.246 r0 bottom
R568 "0mR" "RES 0402/1005 RF" 201.411,147.249 r0 bottom
R569 "0mR" "RES 0402/1005 RF" 265.855,182.786 r180 bottom
R570 "0mR" "RES 0402/1005 RF" 265.855,183.751 r180 bottom
R571 "0mR" "RES 0402/1005 RF" 265.855,181.846 r180 bottom
R572 "0mR" "RES 0402/1005 RF" 265.855,180.907 r180 bottom
R573 "0mR" "RES 0402/1005 RF" 268.605,182.786 r0 bottom
R574 "0mR" "RES 0402/1005 RF" 268.605,183.751 r0 bottom
R575 "0mR" "RES 0402/1005 RF" 268.605,181.846 r0 bottom
R576 "0mR" "RES 0402/1005 RF" 268.605,180.907 r0 bottom
R577 "0mR" "RES 0402/1005 RF" 218.852,140.072 r180 bottom
R578 "0mR" "RES 0402/1005 RF" 218.852,141.279 r180 bottom
R579 "0mR" "RES 0402/1005 RF" 218.852,138.865 r180 bottom
R580 "0mR" "RES 0402/1005 RF" 218.852,137.658 r180 bottom
R581 "0mR" "RES 0402/1005 RF" 221.658,140.072 r0 bottom
R582 "0mR" "RES 0402/1005 RF" 221.658,141.279 r0 bottom
R583 "0mR" "RES 0402/1005 RF" 221.658,138.865 r0 bottom
R584 "0mR" "RES 0402/1005 RF" 221.647,137.658 r0 bottom
R585 "0mR" "RES 0402/1005 RF" 219.893,124.855 r270 bottom
R586 "0mR" "RES 0402/1005 RF" 218.851,124.855 r270 bottom
R587 "0mR" "RES 0402/1005 RF" 220.909,124.855 r270 bottom
R588 "0mR" "RES 0402/1005 RF" 221.959,124.855 r270 bottom
R589 "0mR" "RES 0402/1005 RF" 219.893,127.328 r90 bottom
R590 "0mR" "RES 0402/1005 RF" 218.861,127.328 r90 bottom
R591 "0mR" "RES 0402/1005 RF" 220.909,127.328 r90 bottom
R592 "0mR" "RES 0402/1005 RF" 221.959,127.333 r90 bottom
R593 "0mR" "RES 0402/1005 RF" 58.339,44.108 r90 bottom
R594 "0mR" "RES 0402/1005 RF" 57.264,44.104 r90 bottom
R595 "0mR" "RES 0402/1005 RF" 59.434,41.45 r270 bottom
R596 "0mR" "RES 0402/1005 RF" 60.53,41.45 r270 bottom
R597 "0mR" "RES 0402/1005 RF" 58.339,41.45 r270 bottom
R598 "0mR" "RES 0402/1005 RF" 57.264,41.45 r270 bottom
R599 "1kR" "RES 0402/1005 RF" 360.883,28.042 r90 top
R600 "0mR" "RES 0402/1005 RF" 367.741,34.29 r90 top
R601 "0mR" "RES 0402/1005 RF" 360.883,34.29 r90 top
R602 "10kR" "RES 0402/1005 RF" 378.714,52.959 r0 top
R603 "10kR" "RES 0402/1005 RF" 374.383,52.959 r0 top
R604 "10kR" "RES 0402/1005 RF" 370.053,52.959 r0 top
R605 "10kR" "RES 0402/1005 RF" 365.722,52.959 r0 top
R606 "10kR" "RES 0402/1005 RF" 361.391,52.959 r0 top
R607 "0mR" "RES 0402/1005 RF" 390.347,28.042 r90 top
R608 "10kR" "RES 0402/1005 RF" 365.722,27.521 r0 top
R609 "10kR" "RES 0402/1005 RF" 358.267,30.759 r0 top
R610 "1.33kR" "RES 0402/1005 RF" 118.096,45.463 r180 top
R611 "1.33kR" "RES 0402/1005 RF" 127.519,45.198 r0 top
R612 "270R" "RES 0402/1005 RF" 116.226,37.426 r270 top
R613 "2.4R" "RES 1206/3216" 112.233,68.85 r0 top
R614 "270R" "RES 0402/1005 RF" 127.404,37.326 r270 top
R615 "10kR" "RES 0402/1005 RF" 123.378,38.69 r90 bottom
R616 "2.4R" "RES 1206/3216" 132.685,68.801 r180 top
R617 "PU5931FKMP70R004L" PU5931 157.952,100.98 r90 top
R618 "10kR" "RES 0402/1005 RF" 476.987,46.507 r90 top
R619 "1.91kR" "RES 0402/1005 RF" 209.916,44.86 r90 top
R620 "2kR" "RES 0402/1005 RF" 217.055,44.86 r90 top
R621 "147kR" "RES 0402/1005 RF" 201.462,52.737 r180 top
R622 "340kR" "RES 0402/1005 RF" 225.397,52.437 r0 top
R623 "1.43kR" "RES 0402/1005 RF" 217.655,40.305 r180 top
R624 "15kR" "RES 0402/1005 RF" 209.351,40.359 r0 top
R625 "1.4kR" "RES 0201/0603" 161.943,42.063 r0 top
R626 "200kR" "RES 0402/1005 RF" 162.337,35.058 r180 top
R627 "10.5kR" "RES 0402/1005 RF" 162.314,36.005 r0 top
R628 "750kR" "RES 0402/1005 RF" 177.372,50.245 r0 top
R629 "Resistance" "RES 0402/1005 RF" 165.533,43.718 r270 top
R630 "10kR" "RES 0402/1005 RF" 67.085,28.871 r90 top
R631 "5.9kR" "RES 0402/1005 RF" 170.224,37 r180 top
R632 "100kR" "RES 0402/1005 RF" 180.547,132.705 r90 top
R633 "100kR" "RES 0402/1005 RF" 180.597,127.878 r90 top
R634 "100kR" "RES 0402/1005 RF" 180.597,122.669 r90 top
R635 "10k" "RES 0402/1005 RF" 468.147,29.337 r0 top
R636 "0R" "RES 0402/1005 RF" 463.817,29.337 r0 top
R637 "0R" "RES 0402/1005 RF" 459.486,29.337 r0 top
R638 "0R" "RES 0402/1005 RF" 455.168,29.337 r0 top
R639 "0R" "RES 0402/1005 RF" 450.837,29.337 r0 top
R640 "0R" "RES 0402/1005 RF" 446.507,29.337 r0 top
R641 "0R" "RES 0402/1005 RF" 442.176,29.337 r0 top
R642 "0R" "RES 0402/1005 RF" 437.845,29.337 r0 top
R643 "0R" "RES 0402/1005 RF" 433.514,29.337 r0 top
R644 "9.1kR" "RES 0402/1005 RF" 158.898,149.862 r270 top
R645 "13kR" "RES 0402/1005 RF" 158.898,151.95 r270 top
R646 "100kR" "RES 0402/1005 RF" 156.588,152.612 r90 top
R647 "100kR" "RES 0402/1005 RF" 421.348,41.44 r0 top
R648 "2R" "RES 0402/1005 RF" 425.666,41.44 r0 top
R649 "10kR" "RES 0402/1005 RF" 417.017,41.44 r0 top
R650 "100MR" "RES 0402/1005 RF" 412.686,41.44 r0 top
R651 "10kR" "RES 0402/1005 RF" 408.356,41.44 r0 top
R652 "1MR" "RES 0402/1005 RF" 404.025,41.44 r0 top
R653 "20R" "RES 0402/1005 RF" 393.522,41.44 r0 top
R654 "100R" "RES 0402/1005 RF" 389.204,41.44 r0 top
R655 "10kR" "RES 0402/1005 RF" 378.701,41.44 r0 top
R656 "10kR" "RES 0402/1005 RF" 374.371,41.44 r0 top
R657 "100R" "RES 0402/1005 RF" 370.04,41.44 r0 top
R658 "10kR" "RES 0402/1005 RF" 365.709,41.44 r0 top
R659 "10kR" "RES 0402/1005 RF" 469.621,46.507 r90 top
R660 "10kR" "RES 0402/1005 RF" 462.255,46.507 r90 top
R661 "10kR" "RES 0402/1005 RF" 455.397,46.507 r90 top
R662 "10kR" "RES 0402/1005 RF" 448.031,46.507 r90 top
R663 "10kR" "RES 0402/1005 RF" 440.665,46.507 r90 top
R664 "10kR" "RES 0402/1005 RF" 433.299,46.507 r90 top
R665 "0mR" "RES 0402/1005 RF" 58.128,77.884 r180 top
R666 "12mR" "RES 1206/3216" 78.313,71.605 r0 top
R667 "24.9kR" "RES 0402/1005 RF" 50.946,77.43 r90 top
R668 "20kR" "RES 0402/1005 RF" 360.883,168.402 r90 top
R669 "0mR" "RES 0402/1005 RF" 48.076,81.086 r90 top
R670 "0mR" "RES 0402/1005 RF" 49.059,82.536 r90 top
R671 "1.87kR" "RES 0402/1005 RF" 301.054,174.47 r0 top
R672 "1.5kR" "RES 0402/1005 RF" 299.259,175.27 r270 top
R673 "1.87kR" "RES 0402/1005 RF" 301.218,168.891 r180 top
R674 "15kR" "RES 0402/1005 RF" 302.202,167.138 r180 top
R675 "0mR" "RES 0402/1005 RF" 114.926,111.784 r0 top
R676 "20kR" "RES 0402/1005 RF" 300.104,167.138 r0 top
R677 "95.3kR" "RES 0402/1005 RF" 66.785,35.022 r180 top
R678 "95.3kR" "RES 0402/1005 RF" 66.785,35.972 r180 top
R679 "95.3kR" "RES 0402/1005 RF" 69.299,34.041 r0 top
R680 "95.3kR" "RES 0402/1005 RF" 69.309,36.052 r0 top
R681 "24.9kR" "RES 0402/1005 RF" 68.053,28.871 r90 top
R682 "7.5kR" "RES 0402/1005 RF" 66.785,34.081 r0 top
R683 "4.87kR" "RES 0402/1005 RF" 66.785,36.958 r0 top
R684 "7.15kR" "RES 0402/1005 RF" 69.309,35.032 r180 top
R685 "5.9kR" "RES 0402/1005 RF" 69.303,37.017 r180 top
R686 "412kR" "RES 0402/1005 RF" 155.203,50.245 r180 top
R687 "57.6kR" "RES 0402/1005 RF" 161.778,37.015 r0 top
R688 "10kR" "RES 0402/1005 RF" 425.933,46.507 r90 top
R689 "20kR" "RES 0402/1005 RF" 219.964,211.107 r270 top
R690 "100kR" "RES 0402/1005 RF" 220.929,211.107 r270 top
R691 "20kR" "RES 0402/1005 RF" 213.741,209.232 r270 top
R692 "0R" "RES 0402/1005 RF" 367.309,172.187 r90 top
R693 "0mR" "RES 0402/1005 RF" 400.202,202.641 r90 top
R694 "1kR" "RES 0402/1005 RF" 386.969,202.641 r90 top
R695 "100R" "RES 0402/1005 RF" 368.249,202.641 r90 top
R696 "0mR" "RES 0402/1005 RF" 360.883,202.641 r90 top
R697 "0mR" "RES 0402/1005 RF" 476.679,229.356 r180 top
R698 "0mR" "RES 0402/1005 RF" 479.43,229.356 r0 top
R699 "0mR" "RES 0402/1005 RF" 476.679,230.362 r180 top
R700 "0mR" "RES 0402/1005 RF" 479.43,230.362 r0 top
R701 "0mR" "RES 0402/1005 RF" 476.679,231.39 r180 top
R702 "0mR" "RES 0402/1005 RF" 479.43,231.39 r0 top
R703 "0mR" "RES 0402/1005 RF" 492.506,251.174 r180 top
R704 "0mR" "RES 0402/1005 RF" 495.219,251.174 r0 top
R705 "0mR" "RES 0402/1005 RF" 492.506,252.139 r180 top
R706 "0mR" "RES 0402/1005 RF" 495.219,252.139 r0 top
R707 "0mR" "RES 0402/1005 RF" 492.506,253.124 r180 top
R708 "0mR" "RES 0402/1005 RF" 495.219,253.124 r0 top
R709 "2.2kR" "RES 0402/1005 RF" 422.707,76.022 r90 top
R710 "10kR" "RES 0402/1005 RF" 408.229,76.022 r90 top
R711 "0mR" "RES 0402/1005 RF" 388.645,76.022 r90 top
R712 "0mR" "RES 0402/1005 RF" 395.249,76.022 r90 top
R713 "0mR" "RES 0402/1005 RF" 375.107,76.022 r90 top
R714 "2.2kR" "RES 0402/1005 RF" 367.995,76.022 r90 top
R715 "10kR" "RES 0402/1005 RF" 360.883,76.022 r90 top
R716 "261R" "RES 0402/1005 RF" 394.056,113.081 r90 top
R717 "261R" "RES 0402/1005 RF" 386.944,113.081 r90 top
R718 "261R" "RES 0402/1005 RF" 379.832,113.081 r90 top
R719 "261R" "RES 0402/1005 RF" 372.72,113.081 r90 top
R720 "261R" "RES 0402/1005 RF" 365.354,113.081 r90 top
R721 "10k" "RES 0402/1005 RF" 484.683,56.236 r90 top
R722 "0R" "RES 0402/1005 RF" 477.317,56.236 r90 top
R723 "0R" "RES 0402/1005 RF" 469.951,56.236 r90 top
R724 "0R" "RES 0402/1005 RF" 462.585,56.236 r90 top
R725 "0R" "RES 0402/1005 RF" 455.219,56.236 r90 top
R726 "0R" "RES 0402/1005 RF" 447.853,56.236 r90 top
R727 "0R" "RES 0402/1005 RF" 440.487,56.236 r90 top
R728 "0R" "RES 0402/1005 RF" 433.121,56.236 r90 top
R729 "0R" "RES 0402/1005 RF" 425.755,56.236 r90 top
R730 "4.7kR" "RES 0402/1005 RF" 389.407,56.236 r90 top
R731 "4.7kR" "RES 0402/1005 RF" 396.799,56.236 r90 top
R732 "4.7kR" "RES 0402/1005 RF" 403.657,56.236 r90 top
R733 "4.7kR" "RES 0402/1005 RF" 411.023,56.236 r90 top
R734 "4.7kR" "RES 0402/1005 RF" 418.389,56.236 r90 top
R735 "10kR" "RES 0402/1005 RF" 360.883,40.056 r90 top
R736 "0mR" "RES 0402/1005 RF" 382.981,28.042 r90 top
R737 "10kR" "RES 0402/1005 RF" 106.856,111.784 r0 top
R738 "0mR" "RES 0402/1005 RF" 494.067,229.065 r180 top
R739 "0mR" "RES 0402/1005 RF" 496.783,229.065 r0 top
R740 "0mR" "RES 0402/1005 RF" 494.067,230.174 r180 top
R741 "0mR" "RES 0402/1005 RF" 496.783,230.174 r0 top
R742 "0mR" "RES 0402/1005 RF" 494.067,231.199 r180 top
R743 "0mR" "RES 0402/1005 RF" 496.783,231.199 r0 top
R744 "10kR" "RES 0402/1005 RF" 418.567,46.507 r90 top
R745 "20kR" "RES 0402/1005 RF" 298.709,176.805 r0 top
R746 "10kR" "RES 0402/1005 RF" 101.476,108.468 r0 top
R747 "10kR" "RES 0402/1005 RF" 109.546,106.81 r0 top
R748 "10kR" "RES 0402/1005 RF" 104.166,108.468 r0 top
R749 "10kR" "RES 0402/1005 RF" 98.786,108.468 r0 top
R750 "10kR" "RES 0402/1005 RF" 101.476,105.152 r0 top
R751 "10kR" "RES 0402/1005 RF" 109.546,105.152 r0 top
R752 "10kR" "RES 0402/1005 RF" 112.236,108.468 r0 top
R753 "10kR" "RES 0402/1005 RF" 98.786,105.152 r0 top
R754 "10kR" "RES 0402/1005 RF" 114.926,106.81 r0 top
R755 "10kR" "RES 0402/1005 RF" 101.476,106.81 r0 top
R756 "10kR" "RES 0402/1005 RF" 109.546,108.468 r0 top
R757 "10kR" "RES 0402/1005 RF" 112.236,106.81 r0 top
R758 "0mR" "RES 0402/1005 RF" 477.763,197.199 r180 top
R759 "0mR" "RES 0402/1005 RF" 480.654,197.189 r0 top
R760 "0mR" "RES 0402/1005 RF" 477.764,198.206 r180 top
R761 "0mR" "RES 0402/1005 RF" 480.654,198.196 r0 top
R762 "0mR" "RES 0402/1005 RF" 477.764,199.196 r180 top
R763 "0mR" "RES 0402/1005 RF" 480.654,199.187 r0 top
R764 "WSHP28184L000FEA" WSHP2818 65.796,93.023 r270 top
R765 "0mR" "RES 0402/1005 RF" 375.615,28.042 r90 top
R766 "0mR" "RES 0402/1005 RF" 368.249,28.042 r90 top
R767 "0mR" "RES 0402/1005 RF" 359.221,28.339 r90 top
R768 "0mR" "RES 0402/1005 RF" 710.209,34.29 r90 top
R769 "0mR" "RES 0402/1005 RF" 702.843,34.29 r90 top
R770 "0mR" "RES 0402/1005 RF" 695.477,34.29 r90 top
R771 "0mR" "RES 0402/1005 RF" 688.619,34.29 r90 top
R772 "0mR" "RES 0402/1005 RF" 681.253,34.29 r90 top
R773 "0mR" "RES 0402/1005 RF" 673.887,34.29 r90 top
R774 "0mR" "RES 0402/1005 RF" 666.521,34.29 r90 top
R775 "0mR" "RES 0402/1005 RF" 659.155,34.29 r90 top
R776 "0mR" "RES 0402/1005 RF" 651.789,34.29 r90 top
R777 "0mR" "RES 0402/1005 RF" 644.423,34.29 r90 top
R778 "0mR" "RES 0402/1005 RF" 637.057,34.29 r90 top
R779 "0mR" "RES 0402/1005 RF" 629.691,34.29 r90 top
R780 "0mR" "RES 0402/1005 RF" 622.325,34.29 r90 top
R781 "0mR" "RES 0402/1005 RF" 615.467,34.29 r90 top
R782 "0mR" "RES 0402/1005 RF" 608.076,34.29 r90 top
R783 "0mR" "RES 0402/1005 RF" 600.71,34.29 r90 top
R784 "0mR" "RES 0402/1005 RF" 593.344,34.29 r90 top
R785 "0mR" "RES 0402/1005 RF" 585.978,34.29 r90 top
R786 "0mR" "RES 0402/1005 RF" 578.612,34.29 r90 top
R787 "0mR" "RES 0402/1005 RF" 571.246,34.29 r90 top
R788 "0mR" "RES 0402/1005 RF" 563.88,34.29 r90 top
R789 "0mR" "RES 0402/1005 RF" 556.514,34.29 r90 top
R790 "0mR" "RES 0402/1005 RF" 549.148,34.29 r90 top
R791 "0mR" "RES 0402/1005 RF" 542.29,34.29 r90 top
R792 "0mR" "RES 0402/1005 RF" 534.924,34.29 r90 top
R793 "0mR" "RES 0402/1005 RF" 527.558,34.29 r90 top
R794 "0mR" "RES 0402/1005 RF" 520.192,34.29 r90 top
R795 "0mR" "RES 0402/1005 RF" 512.826,34.29 r90 top
R796 "0mR" "RES 0402/1005 RF" 505.46,34.29 r90 top
R797 "0mR" "RES 0402/1005 RF" 498.069,34.29 r90 top
R798 "0mR" "RES 0402/1005 RF" 490.703,34.29 r90 top
R799 "0mR" "RES 0402/1005 RF" 483.337,34.29 r90 top
R800 "0mR" "RES 0402/1005 RF" 475.971,34.29 r90 top
R801 "0mR" "RES 0402/1005 RF" 469.113,34.29 r90 top
R802 "0mR" "RES 0402/1005 RF" 461.747,34.29 r90 top
R803 "0mR" "RES 0402/1005 RF" 454.381,34.29 r90 top
R804 "0mR" "RES 0402/1005 RF" 447.015,34.29 r90 top
R805 "0mR" "RES 0402/1005 RF" 439.649,34.29 r90 top
R806 "0mR" "RES 0402/1005 RF" 432.283,34.29 r90 top
R807 "0mR" "RES 0402/1005 RF" 424.917,34.29 r90 top
R808 "0mR" "RES 0402/1005 RF" 417.551,34.29 r90 top
R809 "0mR" "RES 0402/1005 RF" 410.185,34.29 r90 top
R810 "0mR" "RES 0402/1005 RF" 403.073,34.29 r90 top
R811 "0mR" "RES 0402/1005 RF" 396.443,34.29 r90 top
R812 "0mR" "RES 0402/1005 RF" 389.331,34.29 r90 top
R813 "0mR" "RES 0402/1005 RF" 382.219,34.29 r90 top
R814 "0mR" "RES 0402/1005 RF" 375.107,34.29 r90 top
R815 "0mR" "RES 0402/1005 RF" 367.995,34.29 r90 top
R816 "0mR" "RES 0402/1005 RF" 360.883,34.29 r90 top
R817 "10kR" "RES 0402/1005 RF" 411.455,46.507 r90 top
R818 "10kR" "RES 0402/1005 RF" 404.343,46.507 r90 top
R819 "10kR" "RES 0402/1005 RF" 397.205,46.507 r90 top
R820 "10kR" "RES 0402/1005 RF" 389.839,46.507 r90 top
R821 "10kR" "RES 0402/1005 RF" 382.981,46.507 r90 top
R822 "10kR" "RES 0402/1005 RF" 375.615,46.507 r90 top
R823 "10kR" "RES 0402/1005 RF" 368.249,46.507 r90 top
R824 "10kR" "RES 0402/1005 RF" 360.883,46.507 r90 top
R832 "100kR" "RES 0402/1005 RF" 426.695,28.042 r90 top
R833 "10kR" "RES 0402/1005 RF" 419.329,28.042 r90 top
R834 "10kR" "RES 0402/1005 RF" 411.963,28.042 r90 top
R835 "100kR" "RES 0402/1005 RF" 404.597,28.042 r90 top
R836 "10kR" "RES 0402/1005 RF" 397.205,28.042 r90 top
R837 "10kR" "RES 0402/1005 RF" 389.839,28.042 r90 top
R838 "20kR" "RES 0402/1005 RF" 382.473,28.042 r90 top
R839 "10kR" "RES 0402/1005 RF" 375.107,28.042 r90 top
R840 "20kR" "RES 0402/1005 RF" 367.741,28.042 r90 top
R841 "20kR" "RES 0402/1005 RF" 360.883,28.042 r90 top
S1 "Mode Switch" SO8_N 229.603,223.774 r180 top
S2 "430181038816" 430181038816 402.45,61.481 r90 top
S3 "430181038816" 430181038816 397.015,61.951 r90 top
S4 "430181038816" 430181038816 389.433,63.233 r90 top
S5 "Mode Switch" SO8_N 382.27,20.13 r0 top
S6 "430181038816" 430181038816 362.89,168.529 r90 top
S7 "430181038816" 430181038816 384.226,72.365 r90 top
T5 "BSC080N03LSG" BSC080N03LS 111.494,62.061 r180 top
T6 "BSC080N03LSG" BSC080N03LS 111.494,55.061 r180 top
T7 "BSC030N03LS-G" BSC030N03LS 118.727,55.061 r180 top
T8 "BSC030N03LS-G" BSC030N03LS 118.727,62.061 r180 top
T9 "BSC080N03LSG" BSC080N03LS 133.515,62.061 r0 top
T10 "BSC080N03LSG" BSC080N03LS 133.515,55.061 r0 top
T11 "BSC030N03LS-G" BSC030N03LS 126.252,62.061 r0 top
T12 "BSC030N03LS-G" BSC030N03LS 126.252,55.061 r0 top
T13 "BSC080N03LSG" BSC080N03LS 200.343,57.051 r180 top
T14 "BSC030N03LS-G" BSC030N03LS 207.929,57.051 r180 top
T15 "BSC080N03LSG" BSC080N03LS 226.617,57.083 r0 top
T16 "BSC030N03LS-G" BSC030N03LS 219.085,57.083 r0 top
T17 "BSC080N03LSG" BSC080N03LS 153.359,53.955 r180 top
T18 "BSC030N03LS-G" BSC030N03LS 160.988,53.955 r180 top
T19 "BSC080N03LSG" BSC080N03LS 178.772,54.055 r0 top
T20 "BSC030N03LS-G" BSC030N03LS 170.916,54.055 r0 top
